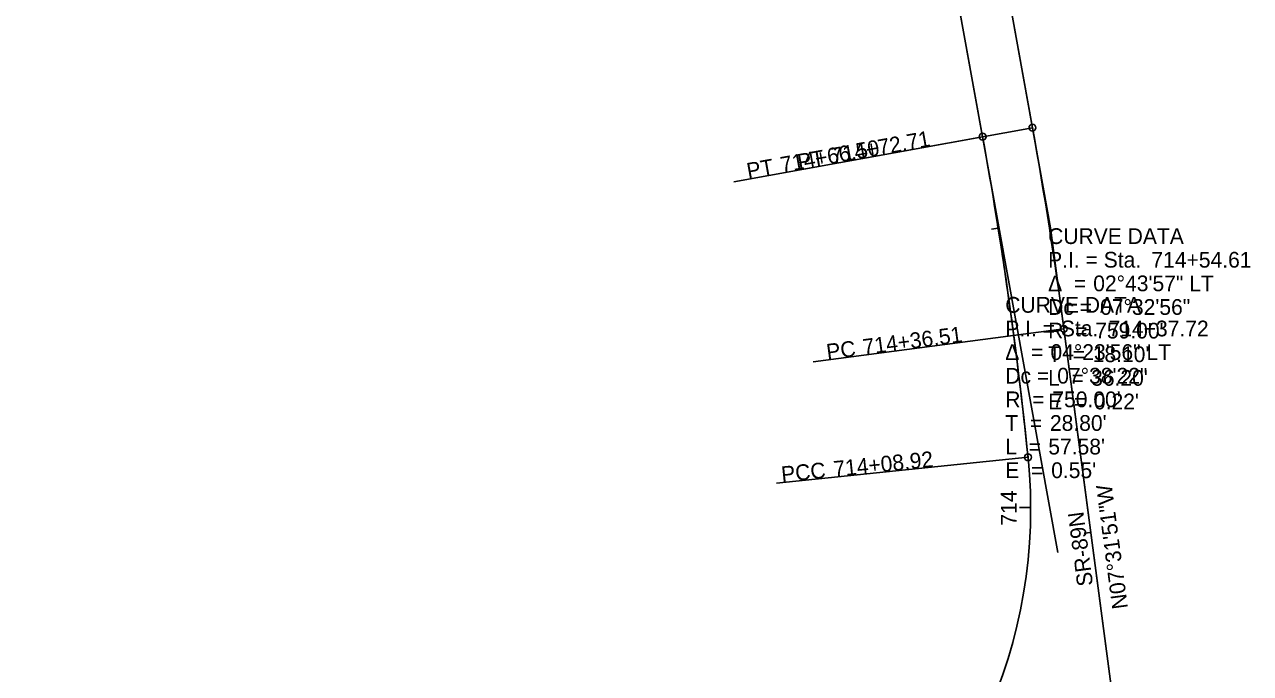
# Model space of a CAD drawing. Extents: x 2047151 to 2048731, y 456453 to 457874.
# Drawn here: x 2047496.9 to 2047714.9, y 457107.4 to 457222.8 of the extents above; entities that cross this region are included whole.
import ezdxf

# ---------------------------------------------------------------- set-up
doc = ezdxf.new("R2010")
doc.units = 0
for name, color, linetype in [('GE_P_Alignment', 7, 'Continuous'), ('GE_P_Alignment_100_Cardinal_Points', 7, 'Continuous'), ('GE_P_Alignment_100_Curve_Data', 7, 'Continuous'), ('GE_P_Alignment_100_Stations', 7, 'Continuous'), ('GE_P_Alignment_500_Bearings', 7, 'Continuous'), ('GE_P_Alignment_500_Cardinal_Points', 7, 'Continuous'), ('GE_P_Alignment_500_Curve_Data', 7, 'Continuous'), ('GE_P_Alignment_500_Distances', 7, 'Continuous'), ('GE_P_Alignment_500_Stations', 7, 'Continuous')]:
    doc.layers.add(name, color=color, linetype=linetype)

msp = doc.modelspace()

# ---------------------------------------------------------------- linework, layer by layer
at = {"layer": 'GE_P_Alignment'}
for p, q in [((2047679.37, 457186.67), (2047621.14, 457508.26)), ((2047680.68, 457128.93), (2047622.24, 457451.67)), ((2047676.14, 457204.48), (2047648.37, 457357.87)), ((2047667.29, 457202.88), (2047649.47, 457301.28)), ((2047696.03, 457060.66), (2047679.37, 457186.67)), ((2047691.92, 457091.7), (2047681.74, 457168.72))]:
    msp.add_line(p, q, dxfattribs=at)
for centre, radius, start, end in [((2046929.29, 457069.25), 750, 5.83211, 10.26352), ((2046929.29, 457069.25), 750, 5.86473, 10.26352), ((2046929.29, 457069.25), 750, 5.86473, 10.26352), ((2046929.29, 457069.25), 759, 7.53092, 10.26352), ((2046929.29, 457069.25), 759, 7.53092, 10.26352), ((2047585.83, 457136.69), 90, 304.6468, 5.8647), ((2047585.83, 457136.69), 90, 304.6468, 5.8647), ((2047717.44, 458244.57), 1200, 248.79098, 264.8083), ((2047717.44, 458244.57), 1200, 248.79098, 261.16908), ((2047717.44, 458244.57), 1200, 248.79098, 261.16908)]:
    msp.add_arc(centre, radius, start, end, dxfattribs=at)
at = {"layer": 'GE_P_Alignment_100_Cardinal_Points'}
for p, q in [((2047667.29, 457202.88), (2047623.01, 457194.86)), ((2047675.36, 457145.88), (2047630.6, 457141.28))]:
    msp.add_line(p, q, dxfattribs=at)
for centre in [(2047667.29, 457202.88), (2047675.36, 457145.88)]:
    msp.add_circle(centre, 0.6, dxfattribs=at)
at = {"layer": 'GE_P_Alignment_100_Stations'}
for p, q in [((2047670.05, 457186.62), (2047668.86, 457186.43)), ((2047675.83, 457136.98), (2047673.83, 457136.98))]:
    msp.add_line(p, q, dxfattribs=at)
at = {"layer": 'GE_P_Alignment_500_Cardinal_Points'}
for p, q in [((2047676.14, 457204.48), (2047631.86, 457196.47)), ((2047681.74, 457168.72), (2047637.13, 457162.83))]:
    msp.add_line(p, q, dxfattribs=at)
for centre in [(2047676.14, 457204.48), (2047681.74, 457168.72)]:
    msp.add_circle(centre, 0.6, dxfattribs=at)
at = {"layer": 'GE_P_Alignment_500_Stations'}
msp.add_line((2047686.53, 457132.53), (2047685.34, 457132.37), dxfattribs=at)

# ---------------------------------------------------------------- texts
at = {"layer": 'GE_P_Alignment_100_Cardinal_Points'}
for s, rotation, p in [('714+66.50', 10.2635, (2047631.59, 457196.46)), ('PT', 10.2635, (2047625.6, 457195.38)), ('714+08.92', 5.8647, (2047640.9, 457142.39)), ('PCC', 5.8647, (2047631.61, 457141.44))]:
    msp.add_text(s, height=2.8, rotation=rotation, dxfattribs=at).set_placement(p)
at = {"layer": 'GE_P_Alignment_100_Curve_Data'}
for s, p in [('CURVE DATA', (2047671.32, 457171.58)), ('P.I. = Sta. ', (2047671.32, 457167.38)), ('714+37.72', (2047689.69, 457167.38)), ('Δ  = ', (2047671.32, 457163.18)), ('04°23\'56" LT', (2047679.35, 457163.18)), ('Dc = ', (2047671.32, 457158.98)), ('07°38\'22"', (2047680.56, 457158.98)), ('R  = ', (2047671.32, 457154.78)), ("750.00'", (2047679.69, 457154.78)), ('T  = ', (2047671.32, 457150.58)), ("28.80'", (2047679.26, 457150.58)), ('L  = ', (2047671.32, 457146.38)), ("57.58'", (2047678.97, 457146.38)), ('E  = ', (2047671.32, 457142.18)), ("0.55'", (2047679.48, 457142.18))]:
    msp.add_text(s, height=2.8, dxfattribs=at).set_placement(p)
at = {"layer": 'GE_P_Alignment_100_Stations'}
msp.add_text('714', height=2.8, rotation=90.1883, dxfattribs=at).set_placement((2047673.34, 457133.74))
at = {"layer": 'GE_P_Alignment_500_Bearings'}
msp.add_text('N07°31\'51"W', height=2.8, rotation=97.5309, dxfattribs=at).set_placement((2047693.15, 457119.08))
at = {"layer": 'GE_P_Alignment_500_Cardinal_Points'}
for s, rotation, p in [('714+72.71', 10.2635, (2047640.62, 457198.05)), ('PT', 10.2635, (2047634.63, 457196.97)), ('714+36.51', 7.5309, (2047646.16, 457164.07)), ('PC', 7.5309, (2047639.69, 457163.21))]:
    msp.add_text(s, height=2.8, rotation=rotation, dxfattribs=at).set_placement(p)
at = {"layer": 'GE_P_Alignment_500_Curve_Data'}
for s, p in [('CURVE DATA', (2047678.94, 457183.8)), ('P.I. = Sta. ', (2047678.94, 457179.6)), ('714+54.61', (2047697.31, 457179.6)), ('Δ  = ', (2047678.94, 457175.4)), ('02°43\'57" LT', (2047686.96, 457175.4)), ('Dc = ', (2047678.94, 457171.2)), ('07°32\'56"', (2047688.18, 457171.2)), ("759.00'", (2047687.31, 457167)), ('R  = ', (2047678.94, 457167)), ('T  = ', (2047678.94, 457162.8)), ("18.10'", (2047686.87, 457162.8)), ('L  = ', (2047678.94, 457158.6)), ("36.20'", (2047686.59, 457158.6)), ('E  = ', (2047678.94, 457154.4)), ("0.22'", (2047687.09, 457154.4))]:
    msp.add_text(s, height=2.8, dxfattribs=at).set_placement(p)
at = {"layer": 'GE_P_Alignment_500_Distances'}
msp.add_text('SR-89N', height=2.8, rotation=97.5309, dxfattribs=at).set_placement((2047686.94, 457123.15))

doc.saveas('drawing.dxf')
